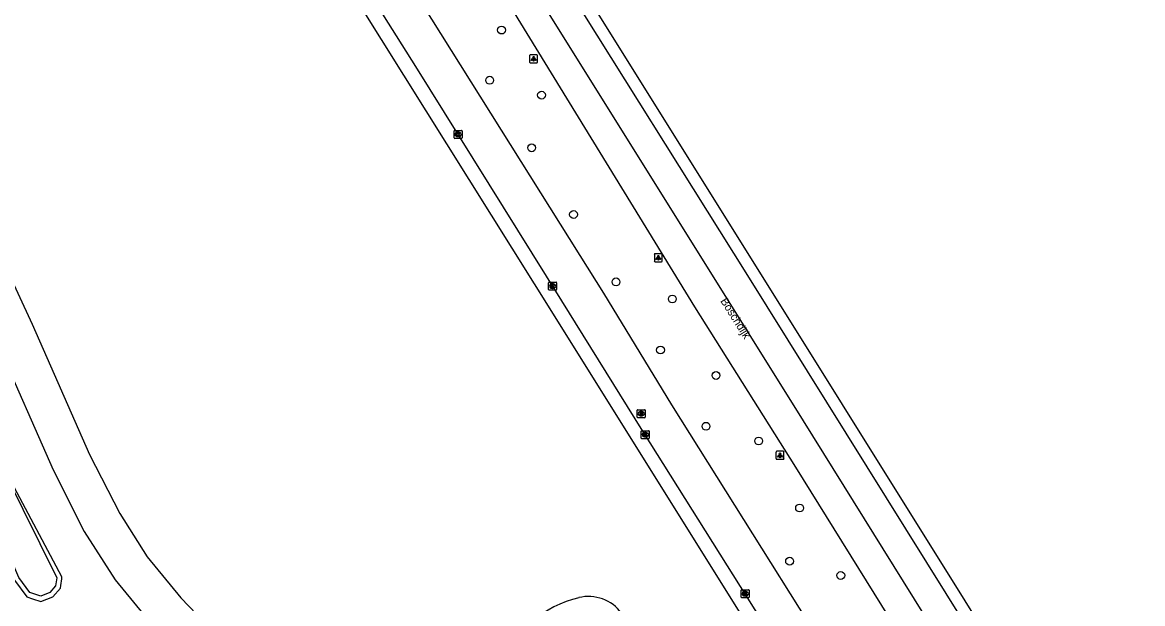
# Model space of a CAD drawing. Extents: x 158132 to 159658, y 385257 to 387209.
# Drawn here: x 159366.9 to 159506.9, y 386170.9 to 386243.5 of the extents above; entities that cross this region are included whole.
import ezdxf

# ---------------------------------------------------------------- set-up
doc = ezdxf.new("R2010")
doc.units = 0
for name, color, linetype in [('IMGEO_Boom', 7, 'Continuous'), ('IMGEO_Groenvoorziening', 7, 'Continuous'), ('IMGEO_Kolk', 7, 'Continuous'), ('IMGEO_Lichtpunt', 7, 'Continuous'), ('IMGEO_Loofbos', 7, 'Continuous'), ('IMGEO_Openbare_ruimte_label', 7, 'Continuous'), ('IMGEO_Rijbaan_lokaal_gesloten', 7, 'Continuous'), ('IMGEO_Rijbaan_lokaal_open', 7, 'Continuous'), ('IMGEO_Rijbaan_regionaal_gesloten', 7, 'Continuous'), ('IMGEO_Rioolput', 7, 'Continuous'), ('IMGEO_Voetpad_open', 7, 'Continuous'), ('IMGEO_Waterloop', 7, 'Continuous')]:
    doc.layers.add(name, color=color, linetype=linetype)

msp = doc.modelspace()

# ---------------------------------------------------------------- linework, layer by layer
at = {"layer": 'IMGEO_Boom'}
for centre in [(159426.75, 386242.55), (159425.27, 386236.28), (159431.75, 386234.42), (159430.52, 386227.84), (159435.75, 386219.5), (159441.06, 386211.08), (159448.1, 386208.95), (159446.62, 386202.57), (159453.56, 386199.39), (159452.31, 386193.04), (159458.89, 386191.2), (159464, 386182.82), (159462.75, 386176.18), (159469.15, 386174.4)]:
    msp.add_circle(centre, 0.489, dxfattribs=at)
at = {"layer": 'IMGEO_Groenvoorziening'}
msp.add_lwpolyline([(159356.58, 386204.92), (159356.01, 386204.62), (159353.53, 386203.46), (159352.96, 386203.19), (159357.68, 386192.44), (159363.21, 386179.89), (159365.87, 386173.83), (159367.41, 386171.72), (159368.14, 386171.48), (159369.19, 386171.14), (159370.69, 386171.72), (159371.63, 386172.83), (159371.68, 386173.13), (159371.8, 386173.99), (159371.82, 386174.23), (159365.53, 386186.05), (159357.82, 386202.63), (159356.71, 386204.68), (159356.58, 386204.92)], dxfattribs=at)
at = {"layer": 'IMGEO_Kolk'}
for p, q in [((159420.82, 386229.08), (159420.82, 386229.94)), ((159420.89, 386230.01), (159421.75, 386230.01)), ((159421.75, 386229.01), (159420.89, 386229.01)), ((159421.33, 386229.23), (159421.3, 386229.23)), ((159421.31, 386229.79), (159421.33, 386229.79)), ((159421.82, 386229.94), (159421.82, 386229.08)), ((159432.64, 386210.13), (159432.64, 386210.98)), ((159432.71, 386211.05), (159433.56, 386211.05)), ((159433.12, 386210.83), (159433.15, 386210.83)), ((159433.64, 386210.98), (159433.64, 386210.13)), ((159433.56, 386210.05), (159432.71, 386210.05)), ((159433.15, 386210.27), (159433.12, 386210.27)), ((159444.21, 386191.56), (159444.21, 386192.42)), ((159444.28, 386192.49), (159445.14, 386192.49)), ((159445.21, 386192.42), (159445.21, 386191.56)), ((159445.14, 386191.49), (159444.28, 386191.49)), ((159444.72, 386191.71), (159444.69, 386191.71)), ((159444.7, 386192.27), (159444.72, 386192.27)), ((159456.7, 386171.69), (159456.7, 386172.54)), ((159456.77, 386172.61), (159457.63, 386172.61)), ((159457.63, 386171.61), (159456.77, 386171.61)), ((159457.19, 386172.39), (159457.21, 386172.39)), ((159457.21, 386171.83), (159457.19, 386171.83)), ((159457.7, 386172.54), (159457.7, 386171.69))]:
    msp.add_line(p, q, dxfattribs=at)
for points in [[(159420.82, 386229.08), (159420.82, 386229.94)], [(159420.89, 386230.01), (159421.75, 386230.01)], [(159421.75, 386229.01), (159420.89, 386229.01)], [(159421.14, 386229.71), (159421.26, 386229.71), (159421.26, 386229.56), (159421.39, 386229.71), (159421.56, 386229.71), (159421.41, 386229.56), (159421.56, 386229.31), (159421.41, 386229.31), (159421.33, 386229.47), (159421.26, 386229.41), (159421.26, 386229.31), (159421.14, 386229.31), (159421.14, 386229.71)], [(159421.82, 386229.94), (159421.82, 386229.08)], [(159432.64, 386210.13), (159432.64, 386210.98)], [(159432.71, 386211.05), (159433.56, 386211.05)], [(159432.96, 386210.75), (159433.08, 386210.75), (159433.08, 386210.6), (159433.21, 386210.75), (159433.37, 386210.75), (159433.23, 386210.6), (159433.38, 386210.35), (159433.23, 386210.35), (159433.14, 386210.52), (159433.08, 386210.45), (159433.08, 386210.35), (159432.96, 386210.35), (159432.96, 386210.75)], [(159433.64, 386210.98), (159433.64, 386210.13)], [(159433.56, 386210.05), (159432.71, 386210.05)], [(159444.21, 386191.56), (159444.21, 386192.42)], [(159444.28, 386192.49), (159445.14, 386192.49)], [(159445.21, 386192.42), (159445.21, 386191.56)], [(159445.14, 386191.49), (159444.28, 386191.49)], [(159444.53, 386192.19), (159444.65, 386192.19), (159444.65, 386192.04), (159444.78, 386192.19), (159444.95, 386192.19), (159444.8, 386192.04), (159444.95, 386191.79), (159444.8, 386191.79), (159444.72, 386191.95), (159444.65, 386191.89), (159444.65, 386191.79), (159444.53, 386191.79), (159444.53, 386192.19)], [(159456.7, 386171.69), (159456.7, 386172.54)], [(159456.77, 386172.61), (159457.63, 386172.61)], [(159457.63, 386171.61), (159456.77, 386171.61)], [(159457.02, 386172.31), (159457.14, 386172.31), (159457.14, 386172.16), (159457.27, 386172.31), (159457.44, 386172.31), (159457.29, 386172.16), (159457.44, 386171.91), (159457.29, 386171.91), (159457.21, 386172.08), (159457.14, 386172.01), (159457.14, 386171.91), (159457.02, 386171.91), (159457.02, 386172.31)], [(159457.7, 386172.54), (159457.7, 386171.69)]]:
    msp.add_lwpolyline(points, dxfattribs=at)
for centre, start, end in [((159420.9, 386229.93), 91.552, 178.448), ((159420.9, 386229.93), 91.552, 178.448), ((159420.9, 386229.09), 181.552, 268.448), ((159420.9, 386229.09), 181.552, 268.448), ((159421.74, 386229.93), 1.552, 88.448), ((159421.74, 386229.93), 1.552, 88.448), ((159421.74, 386229.09), 271.552, 358.448), ((159421.74, 386229.09), 271.552, 358.448), ((159432.71, 386210.98), 91.552, 178.448), ((159432.71, 386210.98), 91.552, 178.448), ((159433.56, 386210.98), 1.552, 88.448), ((159433.56, 386210.98), 1.552, 88.448), ((159432.71, 386210.13), 181.552, 268.448), ((159432.71, 386210.13), 181.552, 268.448), ((159433.56, 386210.13), 271.552, 358.448), ((159433.56, 386210.13), 271.552, 358.448), ((159444.29, 386192.41), 91.552, 178.448), ((159444.29, 386192.41), 91.552, 178.448), ((159445.13, 386192.41), 1.552, 88.448), ((159445.13, 386192.41), 1.552, 88.448), ((159444.29, 386191.57), 181.552, 268.448), ((159444.29, 386191.57), 181.552, 268.448), ((159445.13, 386191.57), 271.552, 358.448), ((159445.13, 386191.57), 271.552, 358.448), ((159456.78, 386172.54), 91.552, 178.448), ((159456.78, 386172.54), 91.552, 178.448), ((159456.78, 386171.69), 181.552, 268.448), ((159456.78, 386171.69), 181.552, 268.448), ((159457.62, 386172.54), 1.552, 88.448), ((159457.62, 386172.54), 1.552, 88.448), ((159457.62, 386171.69), 271.552, 358.448), ((159457.62, 386171.69), 271.552, 358.448)]:
    msp.add_arc(centre, 0.0765, start, end, dxfattribs=at)
for centre, major_axis, ratio, start_param, end_param in [((159421.31, 386229.51), (-0.387, 0.002), 0.722429, 4.712389, 7.853982), ((159421.33, 386229.51), (-0.39, 0.002), 0.717154, 1.570796, 4.712389), ((159433.12, 386210.55), (-0.387, 0.002), 0.722429, 4.712389, 7.853982), ((159433.15, 386210.55), (-0.39, 0.002), 0.717154, 1.570796, 4.712389), ((159444.7, 386191.99), (-0.387, 0.002), 0.722429, 4.712389, 7.853982), ((159444.72, 386191.99), (-0.39, 0.002), 0.717154, 1.570796, 4.712389), ((159457.19, 386172.11), (-0.387, 0.002), 0.722429, 4.712389, 7.853982), ((159457.21, 386172.11), (-0.39, 0.002), 0.717154, 1.570796, 4.712389)]:
    msp.add_ellipse(centre, major_axis=major_axis, ratio=ratio, start_param=start_param, end_param=end_param, dxfattribs=at)
at = {"layer": 'IMGEO_Lichtpunt'}
for p, q in [((159430.26, 386239.36), (159430.26, 386238.55)), ((159430.26, 386239.36), (159430.26, 386238.55)), ((159431.16, 386239.46), (159430.35, 386239.46)), ((159431.16, 386239.46), (159430.35, 386239.46)), ((159431.26, 386238.55), (159431.26, 386239.36)), ((159431.26, 386238.55), (159431.26, 386239.36)), ((159430.35, 386238.46), (159431.16, 386238.46)), ((159430.35, 386238.46), (159431.16, 386238.46)), ((159445.85, 386214.5), (159445.85, 386213.69)), ((159445.85, 386214.5), (159445.85, 386213.69)), ((159446.75, 386214.59), (159445.94, 386214.59)), ((159446.75, 386214.59), (159445.94, 386214.59)), ((159445.94, 386213.6), (159446.75, 386213.6)), ((159445.94, 386213.6), (159446.75, 386213.6)), ((159446.84, 386213.69), (159446.84, 386214.5)), ((159446.84, 386213.69), (159446.84, 386214.5)), ((159461.05, 386189.81), (159461.05, 386189.01)), ((159461.05, 386189.81), (159461.05, 386189.01)), ((159461.96, 386189.91), (159461.15, 386189.91)), ((159461.96, 386189.91), (159461.15, 386189.91)), ((159462.05, 386189.01), (159462.05, 386189.81)), ((159462.05, 386189.01), (159462.05, 386189.81)), ((159461.15, 386188.91), (159461.96, 386188.91)), ((159461.15, 386188.91), (159461.96, 386188.91))]:
    msp.add_line(p, q, dxfattribs=at)
for points in [[(159430.63, 386239.02), (159430.67, 386239), (159430.49, 386238.73), (159430.45, 386238.76), (159430.63, 386239.02)], [(159430.74, 386238.98), (159430.78, 386238.98), (159430.78, 386238.65), (159430.74, 386238.65), (159430.74, 386238.98)], [(159430.85, 386239), (159430.88, 386239.02), (159431.07, 386238.76), (159431.03, 386238.73), (159430.85, 386239)], [(159446.22, 386214.16), (159446.26, 386214.13), (159446.07, 386213.87), (159446.03, 386213.9), (159446.22, 386214.16)], [(159446.32, 386214.11), (159446.37, 386214.11), (159446.37, 386213.79), (159446.32, 386213.79), (159446.32, 386214.11)], [(159446.43, 386214.13), (159446.47, 386214.16), (159446.66, 386213.9), (159446.62, 386213.87), (159446.43, 386214.13)], [(159461.43, 386189.48), (159461.47, 386189.45), (159461.28, 386189.19), (159461.24, 386189.21), (159461.43, 386189.48)], [(159461.53, 386189.43), (159461.58, 386189.43), (159461.58, 386189.11), (159461.53, 386189.11), (159461.53, 386189.43)], [(159461.64, 386189.45), (159461.68, 386189.48), (159461.87, 386189.21), (159461.83, 386189.19), (159461.64, 386189.45)]]:
    msp.add_lwpolyline(points, dxfattribs=at)
for centre in [(159430.76, 386239.16), (159446.35, 386214.3), (159461.55, 386189.61)]:
    msp.add_circle(centre, 0.0994, dxfattribs=at)
for centre, start, end in [((159430.35, 386239.36), 90, 180), ((159430.35, 386239.36), 90, 180), ((159430.35, 386238.55), 180, 270), ((159430.35, 386238.55), 180, 270), ((159431.16, 386239.36), 0, 90), ((159431.16, 386239.36), 0, 90), ((159431.16, 386238.55), 270, 0), ((159431.16, 386238.55), 270, 360), ((159445.94, 386214.5), 90, 180), ((159445.94, 386214.5), 90, 180), ((159445.94, 386213.69), 180, 270), ((159445.94, 386213.69), 180, 270), ((159446.75, 386214.5), 0, 90), ((159446.75, 386214.5), 0, 90), ((159446.75, 386213.69), 270, 0), ((159446.75, 386213.69), 270, 360), ((159461.15, 386189.81), 90, 180), ((159461.15, 386189.81), 90, 180), ((159461.96, 386189.81), 0, 90), ((159461.96, 386189.81), 0, 90), ((159461.15, 386189.01), 180, 270), ((159461.15, 386189.01), 180, 270), ((159461.96, 386189.01), 270, 0), ((159461.96, 386189.01), 270, 360)]:
    msp.add_arc(centre, 0.0946, start, end, dxfattribs=at)
at = {"layer": 'IMGEO_Loofbos'}
for centre, radius, start, end in [((159439.8, 386157.83), 14.2, 103.7927, 157.1231), ((159437.62, 386166.63), 5.14, 36.4764, 103.4762)]:
    msp.add_arc(centre, radius, start, end, dxfattribs=at)
at = {"layer": 'IMGEO_Rijbaan_lokaal_gesloten'}
for points in [[(159347.95, 386242.83), (159349.74, 386240.01), (159355.85, 386230.05), (159362.16, 386218.49), (159368.1, 386205.79), (159375.26, 386189.51), (159379.04, 386182.13), (159382.46, 386176.74), (159386.67, 386171.61), (159391.65, 386166.38), (159411.61, 386147.59)], [(159343.71, 386240.03), (159345.3, 386237.4), (159351.61, 386227.54), (159359.26, 386213.07), (159363.65, 386203.61), (159370.71, 386187.59), (159374.6, 386179.88), (159378.46, 386173.87), (159383.04, 386168.25), (159388.41, 386162.68), (159409.1, 386143.14)]]:
    msp.add_lwpolyline(points, dxfattribs=at)
at = {"layer": 'IMGEO_Rijbaan_lokaal_open'}
for points in [[(159579.02, 385986.46), (159565.95, 385999.29), (159565.01, 386000.35), (159564.05, 386001.43), (159559.49, 386008.45), (159548.31, 386026.23), (159539.09, 386041.1), (159524.94, 386063.72), (159511.65, 386084.93), (159501.39, 386101.34), (159500, 386103.58), (159470.65, 386150.71), (159444.43, 386192.43), (159432.37, 386211.79), (159416.04, 386237.98), (159408.52, 386250), (159377.54, 386299.63), (159368.42, 386314.26), (159342.27, 386356.54)], [(159579.93, 385993.03), (159575.2, 385998.55), (159569.52, 386004.79), (159563.84, 386011.73), (159559.61, 386017.48), (159556.31, 386022.84), (159540.85, 386047.51), (159529, 386066.43), (159516.81, 386085.74), (159508, 386099.84), (159502.05, 386109.41), (159491.48, 386126.22), (159475.22, 386152.38), (159448.05, 386195.73), (159439.54, 386209.69), (159436.59, 386214.4), (159414.26, 386250), (159392.53, 386284.71), (159360.58, 386336.26)]]:
    msp.add_lwpolyline(points, dxfattribs=at)
at = {"layer": 'IMGEO_Rijbaan_regionaal_gesloten'}
for points in [[(159342.02, 386399.64), (159351.36, 386384.68), (159358.7, 386372.92), (159383.7, 386332.81), (159412.25, 386287.13), (159435.45, 386250), (159469.32, 386195.75), (159500, 386146.68), (159500.71, 386145.54), (159504.21, 386139.91)], [(159340.68, 386398.8), (159350.35, 386383.31), (159351.38, 386381.66), (159384.22, 386329.19), (159418.21, 386274.6), (159433.62, 386250), (159457.5, 386211.88), (159499.59, 386144.35), (159500, 386143.69), (159502.82, 386139.09)], [(159499.65, 386137.22), (159464.48, 386193.71), (159376.24, 386334.94), (159348.02, 386380.17), (159337.59, 386396.88)], [(159496.38, 386135.29), (159490.64, 386144.47), (159476.21, 386167.57), (159463.53, 386187.91), (159450.9, 386207.96), (159427.26, 386246.56), (159425.1, 386250), (159405.9, 386280.49), (159387.21, 386310.53), (159345.73, 386377.33), (159334.62, 386395.01)]]:
    msp.add_lwpolyline(points, dxfattribs=at)
at = {"layer": 'IMGEO_Rioolput'}
for p, q in [((159443.78, 386195.11), (159444.63, 386195.11)), ((159443.7, 386194.18), (159443.7, 386195.04)), ((159444.63, 386194.11), (159443.78, 386194.11)), ((159444.19, 386194.89), (159444.21, 386194.89)), ((159444.21, 386194.33), (159444.19, 386194.33)), ((159444.7, 386195.04), (159444.7, 386194.18))]:
    msp.add_line(p, q, dxfattribs=at)
for points in [[(159443.78, 386195.11), (159444.63, 386195.11)], [(159443.7, 386194.18), (159443.7, 386195.04)], [(159444.63, 386194.11), (159443.78, 386194.11)], [(159444.29, 386194.81), (159444.04, 386194.81), (159444.04, 386194.41)], [(159444.04, 386194.41), (159444.16, 386194.41), (159444.16, 386194.57), (159444.17, 386194.57)], [(159444.22, 386194.73), (159444.16, 386194.73), (159444.16, 386194.65)], [(159444.16, 386194.65), (159444.21, 386194.65)], [(159444.22, 386194.54), (159444.29, 386194.41), (159444.43, 386194.41), (159444.37, 386194.54)], [(159444.7, 386195.04), (159444.7, 386194.18)]]:
    msp.add_lwpolyline(points, dxfattribs=at)
for centre, radius, start, end in [((159443.78, 386195.03), 0.0765, 91.552, 178.448), ((159443.78, 386195.03), 0.0765, 91.552, 178.448), ((159444.63, 386195.03), 0.0765, 1.552, 88.448), ((159444.63, 386195.03), 0.0765, 1.552, 88.448), ((159443.78, 386194.18), 0.0765, 181.552, 268.448), ((159443.78, 386194.18), 0.0765, 181.552, 268.448), ((159444.17, 386194.52), 0.0533, 26.0293, 88.6989), ((159444.2, 386194.84), 0.19, 274.7715, 282.9687), ((159444.22, 386194.63), 0.0964, 77.0061, 93.1865), ((159444.24, 386194.69), 0.0378, 276.6634, 79.6772), ((159444.29, 386194.7), 0.109, 350.3612, 89.416), ((159444.29, 386194.7), 0.112, 277.5842, 350.9817), ((159444.27, 386194.48), 0.108, 29.5134, 73.7905), ((159444.63, 386194.18), 0.0765, 271.552, 358.448), ((159444.63, 386194.18), 0.0765, 271.552, 358.448)]:
    msp.add_arc(centre, radius, start, end, dxfattribs=at)
for centre, major_axis, ratio, start_param, end_param in [((159444.19, 386194.61), (-0.387, 0.002), 0.722429, 4.712389, 7.853982), ((159444.21, 386194.61), (-0.39, 0.002), 0.717154, 1.570796, 4.712389)]:
    msp.add_ellipse(centre, major_axis=major_axis, ratio=ratio, start_param=start_param, end_param=end_param, dxfattribs=at)
at = {"layer": 'IMGEO_Voetpad_open'}
msp.add_lwpolyline([(159565.37, 385995.91), (159562.79, 386000), (159562.61, 386000.29), (159500, 386100.31), (159430.86, 386210.85), (159406.37, 386250), (159377.74, 386296.22), (159335.56, 386363.38), (159320.93, 386386.67), (159299.26, 386421.42), (159282.86, 386447.72), (159281.62, 386449.7), (159261.29, 386482.19), (159255.64, 386491.24)], dxfattribs=at)
at = {"layer": 'IMGEO_Waterloop'}
msp.add_lwpolyline([(159356.32, 386204.05), (159371.17, 386174.09), (159371.02, 386173.11), (159370.3, 386172.26), (159369.17, 386171.83), (159367.81, 386172.27), (159366.43, 386174.15), (159363.8, 386180.15), (159358.27, 386192.7), (159353.8, 386202.88), (159356.32, 386204.05)], dxfattribs=at)

# ---------------------------------------------------------------- texts
at = {"layer": 'IMGEO_Openbare_ruimte_label'}
msp.add_text('Boschdijk', height=1, rotation=302.1329, dxfattribs=at).set_placement((159454.06, 386208.7))

doc.saveas('drawing.dxf')
